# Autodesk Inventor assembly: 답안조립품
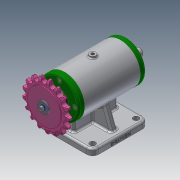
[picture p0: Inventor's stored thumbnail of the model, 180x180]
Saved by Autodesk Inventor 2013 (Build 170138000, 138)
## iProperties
Created: 2019-06
Part Number: 답안조립품
Document SubType Name: Assembly
Designer: user
Author: user
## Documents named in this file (11)
- C:\Users\user\Desktop\490604V1002\답안조립품.iam
- C:\Users\user\Desktop\490604V1002\본체.ipt
- C:\Users\user\Desktop\490604V1002\베어링 6203.ipt
- C:\Users\user\Desktop\490604V1002\볼트 M4.ipt
- C:\Users\user\Desktop\490604V1002\스프로킷.ipt
- C:\Users\user\Desktop\490604V1002\스프링와셔.ipt
- C:\Users\user\Desktop\490604V1002\오일 실 17 30 5.ipt
- C:\Users\user\Desktop\490604V1002\축.ipt
- C:\Users\user\Desktop\490604V1002\커버.ipt
- C:\Users\user\Desktop\490604V1002\키 4x4x12.ipt
- C:\Users\user\Desktop\490604V1002\평와셔.ipt
